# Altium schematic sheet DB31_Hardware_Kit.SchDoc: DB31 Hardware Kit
size A4; Organization: Altium Limited.; Address1: Level 3, 12a Rodborough Rd; Address2: Frenchs Forest 2086; Address3: NSW; Address4: AUSTRALIA; SheetNumber: 8; SheetTotal: 21
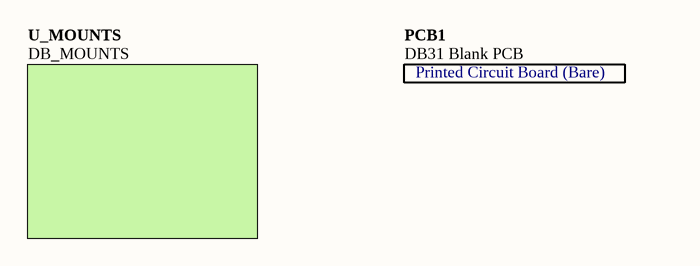
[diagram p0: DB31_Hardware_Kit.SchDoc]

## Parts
PCB1  DB31 Blank PCB  (mechanical)

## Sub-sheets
U_MOUNTS = DB_MOUNTS: no entries

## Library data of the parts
PCB1 = D-810-0005: DB31 Blank PCB - Daughter Board Altera Cyclone2 EP2C35F672C8; ProjectPath: DB31.PrjPCB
